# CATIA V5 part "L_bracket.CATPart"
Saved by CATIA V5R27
Part number: L_bracket
Revision: ANY
Definition: UNKNOWN
Nomenclature: L_bracket
Source: Unknown
Bounding box of the stored display mesh (mm): x 0 to 76.2, y 0 to 76.2, z -16.637 to 16.637
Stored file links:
  \\triton.meca.polymtl.ca\usagers\zaoue\profiles\Desktop\varm_ass\plaque moteur\L_bracket.CATPart
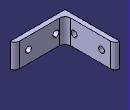
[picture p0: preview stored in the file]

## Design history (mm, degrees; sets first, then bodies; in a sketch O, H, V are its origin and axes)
Body1 "Cut-Extrude2" (main body)
  Solid1: solid without history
